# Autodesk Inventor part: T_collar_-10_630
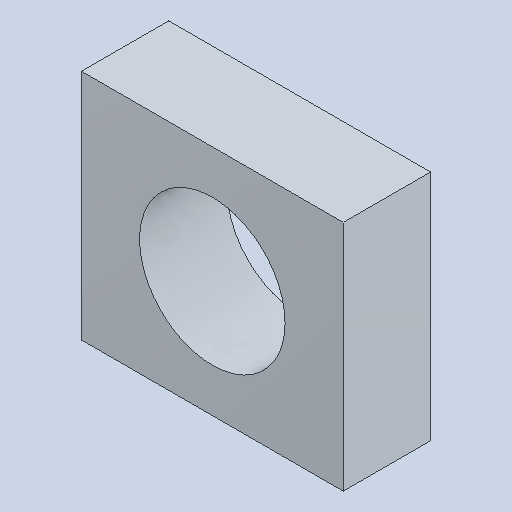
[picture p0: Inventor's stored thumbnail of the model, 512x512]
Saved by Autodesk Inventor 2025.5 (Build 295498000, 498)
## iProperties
Created: 2026-10
Part Number: T_collar_-10_630
Material: Genérico
Document SubType Name: Modeling
Designer: Luis M
Density: 1 g/cm^3
Appearance: Valor por defecto
Author: Luis M
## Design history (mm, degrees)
feature "Base1"
node "Sólido1"
